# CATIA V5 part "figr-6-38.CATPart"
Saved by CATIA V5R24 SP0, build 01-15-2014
Part number: Part1
Bounding box of the stored display mesh (mm): x -42.494 to 42.494, y -51.186 to 51.186, z 0 to 35
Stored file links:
  D:\KAVITA\CATIA V5-6R2014 Project_ Kavita\CATIA V5-6R2014_partfiles\Partfiles\c06_catia_v5-6r2014_prt\figr-6-38.CATPart
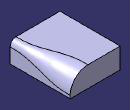
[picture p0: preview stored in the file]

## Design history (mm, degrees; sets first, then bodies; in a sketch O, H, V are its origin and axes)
Body1 (main body)
  Sketch1 on xy-plane, origin (0, 0, 0), H (1, 0, 0), V (0, 1, 0)
    line L1 (-42.4944, 51.1864) -> (42.4944, 51.1864)
    line L2 (42.4944, 51.1864) -> (42.4944, -51.1864)
    line L3 (42.4944, -51.1864) -> (-42.4944, -51.1864)
    line L4 (-42.4944, -51.1864) -> (-42.4944, 51.1864)
    axis line L5 (42.4944, -51.1864) -> (-42.4944, 51.1864)
    horizontal: L1 H, L3 H
    vertical: L2 V, L4 V
    midpoint: O L5
  Pad1: profile Sketch1, direction (0, 0, 1), length 35
  Fillet1: on edge [face of Pad1 | face of Pad1]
